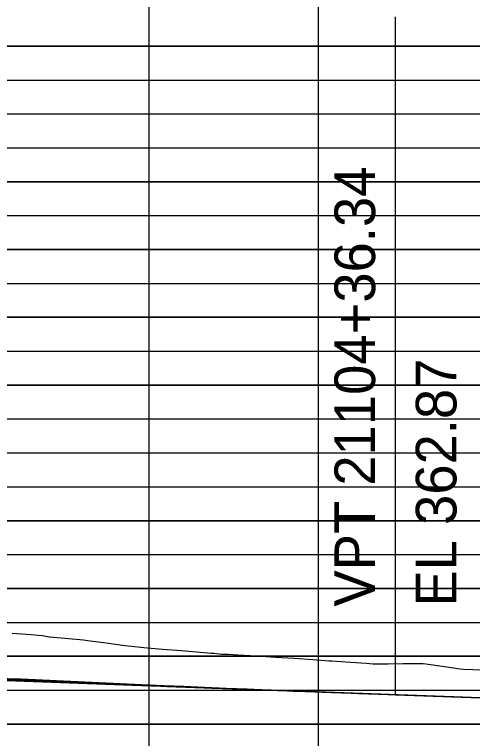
# Model space of a CAD drawing. Extents: x 1195880 to 1289360, y 2059330 to 2086925.
# Drawn here: x 1197386.5 to 1197454.1, y 2059658.6 to 2059765.4 of the extents above; entities that cross this region are included whole.
import ezdxf

# ---------------------------------------------------------------- set-up
doc = ezdxf.new("R2010")
doc.units = 0
for name, color, linetype in [('Default', 7, 'Continuous'), ('Existing Ground PGL', 7, 'Continuous'), ('Grid', 7, 'Continuous'), ('Profile', 7, 'Continuous'), ('Profile Annotation', 7, 'Continuous')]:
    doc.layers.add(name, color=color, linetype=linetype)

msp = doc.modelspace()

# ---------------------------------------------------------------- linework, layer by layer
for p in [(1197367.71, 2059667.81), (1197367.71, 2059667.81), (1197367.71, 2059667.81), (1197409.02, 2059666.3), (1197412.2, 2059666.18), (1197412.71, 2059666.17), (1197415.21, 2059666.07), (1197415.21, 2059666.07), (1197415.21, 2059666.07), (1197415.21, 2059666.07), (1197417.71, 2059665.98), (1197417.71, 2059665.98), (1197428.21, 2059665.6), (1197430.21, 2059665.53), (1197432.71, 2059665.44), (1197435.21, 2059665.34), (1197437.71, 2059665.25), (1197439.21, 2059665.2), (1197440.21, 2059665.16), (1197442.71, 2059665.07)]:
    msp.add_line(p, (1197516.64, 2059662.37))
for points in [[(1197383.96, 2059667.51), (1197386.67, 2059667.37), (1197389.38, 2059667.25), (1197392.08, 2059667.12), (1197394.79, 2059666.99), (1197397.5, 2059666.87), (1197400.21, 2059666.75), (1197402.92, 2059666.63), (1197405.63, 2059666.51), (1197408.33, 2059666.4), (1197411.04, 2059666.28), (1197413.75, 2059666.17), (1197416.46, 2059666.06), (1197419.17, 2059665.95), (1197421.88, 2059665.85), (1197424.58, 2059665.74), (1197427.29, 2059665.64), (1197430, 2059665.53), (1197432.71, 2059665.44)], [(1197384.58, 2059667.49), (1197387.4, 2059667.36), (1197390.21, 2059667.22), (1197393.02, 2059667.09), (1197395.83, 2059666.96), (1197398.65, 2059666.84), (1197401.46, 2059666.71), (1197404.27, 2059666.59), (1197407.08, 2059666.46), (1197409.9, 2059666.34), (1197412.71, 2059666.22), (1197415.52, 2059666.11), (1197418.33, 2059665.99), (1197421.15, 2059665.88), (1197423.96, 2059665.77), (1197426.77, 2059665.66), (1197429.58, 2059665.55), (1197432.4, 2059665.45), (1197435.21, 2059665.34)], [(1197384.92, 2059667.29), (1197386.65, 2059667.21), (1197388.37, 2059667.14), (1197390.09, 2059667.06), (1197391.81, 2059666.99), (1197393.53, 2059666.91), (1197395.25, 2059666.84), (1197396.97, 2059666.77), (1197398.7, 2059666.7), (1197400.42, 2059666.63), (1197402.14, 2059666.56), (1197403.86, 2059666.49), (1197405.58, 2059666.43), (1197407.3, 2059666.36), (1197409.02, 2059666.3)], [(1197385.21, 2059667.48), (1197388.13, 2059667.34), (1197391.04, 2059667.2), (1197393.96, 2059667.07), (1197396.88, 2059666.93), (1197399.79, 2059666.8), (1197402.71, 2059666.67), (1197405.63, 2059666.54), (1197408.54, 2059666.41), (1197411.46, 2059666.29), (1197414.38, 2059666.17), (1197417.29, 2059666.05), (1197420.21, 2059665.93), (1197423.13, 2059665.81), (1197426.04, 2059665.69), (1197428.96, 2059665.58), (1197431.88, 2059665.47), (1197434.79, 2059665.36), (1197437.71, 2059665.25)], [(1197385.36, 2059667.4), (1197387.88, 2059667.29), (1197390.4, 2059667.17), (1197392.92, 2059667.05), (1197395.44, 2059666.94), (1197397.96, 2059666.82), (1197400.48, 2059666.71), (1197403, 2059666.6), (1197405.52, 2059666.5), (1197408.04, 2059666.39), (1197410.56, 2059666.28), (1197413.08, 2059666.18), (1197415.61, 2059666.08), (1197418.13, 2059665.98), (1197420.65, 2059665.88), (1197423.17, 2059665.79), (1197425.69, 2059665.69), (1197428.21, 2059665.6)], [(1197385.52, 2059667.31), (1197387.5, 2059667.21), (1197389.48, 2059667.12), (1197391.46, 2059667.04), (1197393.44, 2059666.95), (1197395.42, 2059666.86), (1197397.4, 2059666.78), (1197399.38, 2059666.69), (1197401.36, 2059666.61), (1197403.33, 2059666.53), (1197405.31, 2059666.45), (1197407.29, 2059666.37), (1197409.27, 2059666.3), (1197411.25, 2059666.22), (1197413.23, 2059666.15), (1197415.21, 2059666.07)], [(1197385.52, 2059667.31), (1197387.5, 2059667.21), (1197389.48, 2059667.12), (1197391.46, 2059667.04), (1197393.44, 2059666.95), (1197395.42, 2059666.86), (1197397.4, 2059666.78), (1197399.38, 2059666.69), (1197401.36, 2059666.61), (1197403.33, 2059666.53), (1197405.31, 2059666.45), (1197407.29, 2059666.37), (1197409.27, 2059666.3), (1197411.25, 2059666.22), (1197413.23, 2059666.15), (1197415.21, 2059666.07)], [(1197385.52, 2059667.31), (1197387.5, 2059667.21), (1197389.48, 2059667.12), (1197391.46, 2059667.04), (1197393.44, 2059666.95), (1197395.42, 2059666.86), (1197397.4, 2059666.78), (1197399.38, 2059666.69), (1197401.36, 2059666.61), (1197403.33, 2059666.53), (1197405.31, 2059666.45), (1197407.29, 2059666.37), (1197409.27, 2059666.3), (1197411.25, 2059666.22), (1197413.23, 2059666.15), (1197415.21, 2059666.07)], [(1197385.52, 2059667.31), (1197387.5, 2059667.21), (1197389.48, 2059667.12), (1197391.46, 2059667.04), (1197393.44, 2059666.95), (1197395.42, 2059666.86), (1197397.4, 2059666.78), (1197399.38, 2059666.69), (1197401.36, 2059666.61), (1197403.33, 2059666.53), (1197405.31, 2059666.45), (1197407.29, 2059666.37), (1197409.27, 2059666.3), (1197411.25, 2059666.22), (1197413.23, 2059666.15), (1197415.21, 2059666.07)], [(1197385.59, 2059667.47), (1197388.57, 2059667.33), (1197391.54, 2059667.19), (1197394.52, 2059667.05), (1197397.5, 2059666.91), (1197400.48, 2059666.78), (1197403.46, 2059666.64), (1197406.44, 2059666.51), (1197409.42, 2059666.38), (1197412.4, 2059666.26), (1197415.38, 2059666.13), (1197418.36, 2059666.01), (1197421.34, 2059665.89), (1197424.32, 2059665.77), (1197427.3, 2059665.65), (1197430.28, 2059665.53), (1197433.26, 2059665.42), (1197436.24, 2059665.31), (1197439.21, 2059665.2)], [(1197385.83, 2059667.47), (1197388.86, 2059667.32), (1197391.88, 2059667.18), (1197394.9, 2059667.04), (1197397.92, 2059666.9), (1197400.94, 2059666.76), (1197403.96, 2059666.63), (1197406.98, 2059666.5), (1197410, 2059666.36), (1197413.02, 2059666.23), (1197416.04, 2059666.11), (1197419.06, 2059665.98), (1197422.08, 2059665.86), (1197425.11, 2059665.74), (1197428.13, 2059665.62), (1197431.15, 2059665.5), (1197434.17, 2059665.39), (1197437.19, 2059665.27), (1197440.21, 2059665.16)], [(1197385.94, 2059667.39), (1197388.54, 2059667.27), (1197391.15, 2059667.15), (1197393.75, 2059667.03), (1197396.36, 2059666.91), (1197398.96, 2059666.79), (1197401.56, 2059666.68), (1197404.17, 2059666.56), (1197406.77, 2059666.45), (1197409.38, 2059666.34), (1197411.98, 2059666.23), (1197414.58, 2059666.13), (1197417.19, 2059666.02), (1197419.79, 2059665.92), (1197422.4, 2059665.82), (1197425, 2059665.72), (1197427.61, 2059665.62), (1197430.21, 2059665.53)], [(1197386.25, 2059667.25), (1197388.1, 2059667.17), (1197389.96, 2059667.08), (1197391.81, 2059667), (1197393.66, 2059666.92), (1197395.52, 2059666.84), (1197397.37, 2059666.76), (1197399.22, 2059666.69), (1197401.08, 2059666.61), (1197402.93, 2059666.54), (1197404.79, 2059666.46), (1197406.64, 2059666.39), (1197408.49, 2059666.32), (1197410.35, 2059666.25), (1197412.2, 2059666.18)], [(1197386.46, 2059667.46), (1197389.58, 2059667.31), (1197392.71, 2059667.16), (1197395.83, 2059667.01), (1197398.96, 2059666.87), (1197402.08, 2059666.73), (1197405.21, 2059666.59), (1197408.33, 2059666.45), (1197411.46, 2059666.31), (1197414.58, 2059666.18), (1197417.71, 2059666.05), (1197420.83, 2059665.92), (1197423.96, 2059665.79), (1197427.08, 2059665.67), (1197430.21, 2059665.54), (1197433.33, 2059665.42), (1197436.46, 2059665.3), (1197439.58, 2059665.19), (1197442.71, 2059665.07)], [(1197386.46, 2059667.28), (1197388.54, 2059667.18), (1197390.63, 2059667.09), (1197392.71, 2059666.99), (1197394.79, 2059666.9), (1197396.88, 2059666.81), (1197398.96, 2059666.72), (1197401.04, 2059666.64), (1197403.13, 2059666.55), (1197405.21, 2059666.46), (1197407.29, 2059666.38), (1197409.38, 2059666.3), (1197411.46, 2059666.22), (1197413.54, 2059666.14), (1197415.63, 2059666.06), (1197417.71, 2059665.98)], [(1197386.46, 2059667.28), (1197388.54, 2059667.18), (1197390.63, 2059667.09), (1197392.71, 2059666.99), (1197394.79, 2059666.9), (1197396.88, 2059666.81), (1197398.96, 2059666.72), (1197401.04, 2059666.64), (1197403.13, 2059666.55), (1197405.21, 2059666.46), (1197407.29, 2059666.38), (1197409.38, 2059666.3), (1197411.46, 2059666.22), (1197413.54, 2059666.14), (1197415.63, 2059666.06), (1197417.71, 2059665.98)], [(1197386.46, 2059667.25), (1197388.33, 2059667.16), (1197390.21, 2059667.08), (1197392.08, 2059666.99), (1197393.96, 2059666.91), (1197395.83, 2059666.83), (1197397.71, 2059666.75), (1197399.58, 2059666.67), (1197401.46, 2059666.6), (1197403.33, 2059666.52), (1197405.21, 2059666.45), (1197407.08, 2059666.38), (1197408.96, 2059666.3), (1197410.83, 2059666.23), (1197412.71, 2059666.17)]]:
    msp.add_lwpolyline(points)
at = {"layer": 'Default'}
msp.add_line((1197516.64, 2059662.37), (1197260.22, 2059671.73), dxfattribs=at)
at = {"layer": 'Existing Ground PGL'}
msp.add_lwpolyline([(1197386.15, 2059674.16), (1197388.92, 2059673.94), (1197390.62, 2059673.81), (1197391.6, 2059673.61), (1197391.7, 2059673.6), (1197394.47, 2059673.34), (1197396.65, 2059673.16), (1197397.25, 2059673.08), (1197400.02, 2059672.71), (1197402.79, 2059672.35), (1197403.74, 2059672.23), (1197405.57, 2059672.06), (1197408.34, 2059671.81), (1197411.12, 2059671.57), (1197413.89, 2059671.34), (1197415.49, 2059671.22), (1197415.98, 2059671.18), (1197416.31, 2059671.17), (1197416.67, 2059671.12), (1197417.03, 2059671.07), (1197418.09, 2059671.06), (1197419.44, 2059670.97), (1197422.21, 2059670.79), (1197424.99, 2059670.62), (1197427.76, 2059670.47), (1197427.8, 2059670.47), (1197430.54, 2059670.25), (1197432.86, 2059670.08), (1197433.31, 2059670.05), (1197436.08, 2059669.88), (1197438.4, 2059669.75), (1197438.86, 2059669.69), (1197439.36, 2059669.62), (1197441.63, 2059669.64), (1197443.8, 2059669.67), (1197444.41, 2059669.67), (1197446.81, 2059669.68), (1197447.18, 2059669.62), (1197449.96, 2059669.21), (1197452.28, 2059668.88), (1197452.73, 2059668.86), (1197455.5, 2059668.75)], dxfattribs=at)
at = {"layer": 'Grid'}
for p, q in [((1197406.37, 2059350.74), (1197406.37, 2059950.74)), ((1197431.37, 2059350.74), (1197431.37, 2059950.74)), ((1197006.37, 2059760.74), (1198006.37, 2059760.74)), ((1198006.37, 2059760.74), (1197006.37, 2059760.74)), ((1197006.37, 2059755.74), (1198006.37, 2059755.74)), ((1197006.37, 2059750.74), (1198006.37, 2059750.74)), ((1197006.37, 2059745.74), (1198006.37, 2059745.74)), ((1197006.37, 2059740.74), (1198006.37, 2059740.74)), ((1198006.37, 2059740.74), (1197006.37, 2059740.74)), ((1197006.37, 2059735.74), (1198006.37, 2059735.74)), ((1197006.37, 2059730.74), (1198006.37, 2059730.74)), ((1198006.37, 2059730.74), (1197006.37, 2059730.74)), ((1197006.37, 2059725.74), (1198006.37, 2059725.74)), ((1197006.37, 2059720.74), (1198006.37, 2059720.74)), ((1198006.37, 2059720.74), (1197006.37, 2059720.74)), ((1197006.37, 2059715.74), (1198006.37, 2059715.74)), ((1197006.37, 2059710.74), (1198006.37, 2059710.74)), ((1198006.37, 2059710.74), (1197006.37, 2059710.74)), ((1197006.37, 2059705.74), (1198006.37, 2059705.74)), ((1197006.37, 2059700.74), (1198006.37, 2059700.74)), ((1197006.37, 2059695.74), (1198006.37, 2059695.74)), ((1197006.37, 2059690.74), (1198006.37, 2059690.74)), ((1198006.37, 2059690.74), (1197006.37, 2059690.74)), ((1197006.37, 2059685.74), (1198006.37, 2059685.74)), ((1197006.37, 2059680.74), (1198006.37, 2059680.74)), ((1198006.37, 2059680.74), (1197006.37, 2059680.74)), ((1197006.37, 2059675.74), (1198006.37, 2059675.74)), ((1197006.37, 2059670.74), (1198006.37, 2059670.74)), ((1198006.37, 2059670.74), (1197006.37, 2059670.74)), ((1197006.37, 2059665.74), (1198006.37, 2059665.74)), ((1197006.37, 2059660.74), (1198006.37, 2059660.74)), ((1198006.37, 2059660.74), (1197006.37, 2059660.74))]:
    msp.add_line(p, q, dxfattribs=at)
at = {"layer": 'Profile'}
msp.add_line((1197442.71, 2059665.07), (1197457.27, 2059664.54), dxfattribs=at)
msp.add_lwpolyline([(1197386.46, 2059667.46), (1197389.58, 2059667.31), (1197392.71, 2059667.16), (1197395.83, 2059667.01), (1197398.96, 2059666.87), (1197402.08, 2059666.73), (1197405.21, 2059666.59), (1197408.33, 2059666.45), (1197411.46, 2059666.31), (1197414.58, 2059666.18), (1197417.71, 2059666.05), (1197420.83, 2059665.92), (1197423.96, 2059665.79), (1197427.08, 2059665.67), (1197430.21, 2059665.54), (1197433.33, 2059665.42), (1197436.46, 2059665.3), (1197439.58, 2059665.19), (1197442.71, 2059665.07)], dxfattribs=at)
at = {"layer": 'Profile Annotation'}
for p, q in [((1197442.71, 2059665.07), (1197442.71, 2059765.07)), ((1197367.71, 2059667.81), (1197405.21, 2059666.44))]:
    msp.add_line(p, q, dxfattribs=at)

# ---------------------------------------------------------------- texts
for s, p in [('VPT 21104+36.34', (1197439.71, 2059678.07)), ('EL 362.87', (1197451.71, 2059678.07))]:
    msp.add_text(s, height=6, rotation=90, dxfattribs=at).set_placement(p)

doc.saveas('drawing.dxf')
